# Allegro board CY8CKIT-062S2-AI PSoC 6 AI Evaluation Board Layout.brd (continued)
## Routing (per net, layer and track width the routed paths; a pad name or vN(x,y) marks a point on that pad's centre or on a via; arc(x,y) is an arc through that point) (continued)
N17076514: length 8
  TOP w0.15: R59.2 18.55,34.41 17.74,33.6 17.74,32 16.42,30.68 16.42,30 16.29,29.87 16.29,29.26 15.38,28.35 U1.N5
N17278110: length 0.9
  BOTTOM w0.15: U20.3 20.55,11.62 R19.2
N17278725: length 1.2
  TOP w0.15: R64.1 8.36,22.91 U3.4
N17278748: length 1.3
  TOP w0.15: U3.3 6.92,22.57 6.92,22.71 6.54,23.09 6.54,23.31 R65.1
N17279219: length 2.9
  TOP w0.15: v1(4.63,40.97) 4.28,41.33 R74.1 4.38,41.55 5.05,41.55 R73.2
  BOTTOM w0.15: v1(4.63,40.97) 4.63,41.27 5.12,41.76 U4.4
N17279342: length 5
  TOP w0.15: v1(29.85,43.99) 29.12,43.26 29.12,42.24 28.78,41.9 R82.1 28.78,41.3 29.32,40.76 R81.2
  BOTTOM w0.15: v1(29.85,43.99) 29.85,43.61 29.7,43.46 U5.4
N17289581: length 2
  BOTTOM w0.15: U7.5 27.04,35.03 27.41,35.03 27.59,34.85 27.9,34.85 28.44,35.39 R88.1
N17289597: length 1.7
  BOTTOM w0.15: R89.1 17.64,33.09 18.09,32.64 18.41,32.64 18.42,32.65 U7.2
N17289613: length 11.9
  BOTTOM w0.15: U7.3 18.33,33.92 18.25,33.83 18.25,33.63 18.55,33.32 19.64,33.32 19.86,33.54 19.86,34.67 19.99,34.8 20.18,34.8 20.31,34.67 20.31,34.05 20.44,33.92 20.72,33.92 20.96,34.16 20.96,34.87 20.68,35.16 20.05,35.16 19.45,35.76 18.22,35.76 17.81,35.36 17.81,34.52 17.64,34.34 R90.1
N17289629: length 1.7
  BOTTOM w0.15: R91.1 28.44,33.02 28,33.02 27.63,32.65 U7.7
N17305257: length 3.7
  TOP w0.229: L3.1 27.2,35.24 26.93,34.98 26.93,34.79 C248.1
  TOP w0.254: U17.31 26.1,35.09 26.61,34.59 C248.1
N17305261: length 3.7
  TOP w0.254: L3.2 26.74,37.64 26.45,37.64 25.79,36.98 24.9,36.98 24.54,36.63 U17.34
N17332525: length 3.4
  TOP w0.18: C246.2 21.39,43.48 L4.1 23.45,43.5 A2.4 A2.1
N17332695: length 9.3
  TOP w0.089: U17.18 23.64,30.21 23.94,29.92 24.16,29.92 24.85,29.24 24.85,28.51 v1(25.25,28.12)
  L04_SIG2 w0.089: v1(28.89,26.29) 28.58,25.98 27.97,25.98 26.06,27.89 25.48,27.89 v1(25.25,28.12)
  BOTTOM w0.089: v1(28.89,26.29) 28.89,26.68 29.16,26.95 TP17.1
N17332709: length 11.9
  TOP w0.089: U17.17 23.19,30 23.48,29.72 24.06,29.72 24.62,29.16 24.62,28.11 v1(24.46,27.95)
  L04_SIG2 w0.089: v1(18.95,26.64) 19.79,27.48 21.54,27.48 22.25,28.19 24.22,28.19 v1(24.46,27.95)
  BOTTOM w0.089: v1(18.95,26.64) 18.62,26.64 18.11,27.15 17.84,27.15 TP19.1
N17332795: length 4.6
  TOP w0.15: U17.10 v1(20.38,31.49)
  L03_SIG1 w0.157: v1(21.09,28.7) 21.09,29.41 20.81,29.69 20.81,31.06 v1(20.38,31.49)
  BOTTOM w0.15: TP28.1 21.27,28.88 v1(21.09,28.7)
N17363073: length 1.7
  TOP w0.15: v1(23.56,7.67) 23.79,7.44 J1.A5
  BOTTOM w0.15: R6.1 23.69,7.53 v1(23.56,7.67)
N17363075: length 1.6
  TOP w0.15: J1.B5 26.79,7.41 v1(26.55,7.65)
  BOTTOM w0.15: R5.1 26.4,7.49 v1(26.55,7.65)
N17373677: length 1.7
  TOP w0.15: J2.A5 8.47,7.57 v1(8.29,7.75)
  BOTTOM w0.15: R18.1 8.37,7.67 v1(8.29,7.75)
N17373681: length 1.6
  TOP w0.15: v1(11.29,7.67) 11.47,7.49 J2.B5
  BOTTOM w0.15: v1(11.29,7.67) 11.29,7.4 R17.1
N17374662: length 10.6
  TOP w0.15: v1(13.01,14.05) 13.32,14.35 13.32,14.54 R297.2 14.05,14.3 D8.K
  L04_SIG2 w0.157: v1(6.48,15.6) 6.79,15.29 11.36,15.29 11.59,15.52 12.07,15.52 13.01,14.58 v1(13.01,14.05)
  BOTTOM w0.15: v1(6.48,15.6) 6.25,15.36 U8.7
N17374666: length 5.2
  TOP w0.15: R1.1 13.45,10.51 13.45,11.98 15.05,13.59 D8.A
N17374668: length 11.6
  TOP w0.15: R2.2 13.24,8.99 13.69,8.54 14.22,8.54 v1(14.67,8.99) 14.95,9.27 R1.2
  L03_SIG1 w0.157: v1(14.67,8.99) 14.33,9.32 14.33,11.68 13.65,12.37 10.78,12.37 10.14,13 v1(10.14,14.12)
N17374688: length 10.3
  TOP w0.15: D11.K 12.89,12.62 v1(12.79,12.73) 12.4,13.11 12.4,14.48 12.71,14.79 R298.2
  L04_SIG2 w0.157: v1(8.01,14.4) 8.36,14.76 10.4,14.76 11.13,14.02 12.2,14.02 12.48,13.74 12.48,13.03 v1(12.79,12.73)
  BOTTOM w0.15: v1(8.01,14.4) 7.91,14.31 U8.9
N17374692: length 1
  TOP w0.15: D11.A R2.1
N17374847: length 1.8
  BOTTOM w0.15: R8.2 4.6,11.9 U8.1
N17374885: length 1
  BOTTOM w0.15: U8.14 6.25,11.73 6.41,11.58 6.41,11.26 R9.2
N17374979: length 5.9
  BOTTOM w0.15: R283.1 4.42,9 4.61,8.81 5.37,8.81 5.55,8.99 5.55,9.79 R13.1 5.54,9.87 5.28,10.13 5.28,10.27 5.15,10.4 5.15,11.04 5.3,11.19 5.52,11.19 R14.1 5.57,11.53 5.75,11.71 U8.15
N17374981: length 1
  BOTTOM w0.15: U8.12 8.28,12.81 R15.1
N17374983: length 1.1
  BOTTOM w0.15: R16.1 5.25,11.74 U8.16
N17378355: length 2.9
  BOTTOM w0.15: U11.10 11,12.45 10.67,12.78 R23.1 R21.2 10.67,14.32 10.78,14.43 10.78,14.92 C253.2
N17378650: length 1.2
  TOP w0.15: R26.2 27.37,10.03 27.14,10.26 D1.A
N17390542: length 0.9
  BOTTOM w0.15: R25.2 23.35,11.62 U21.3
N17394939: length 1.6
  BOTTOM w0.15: U11.6 11,9.8 10.49,9.29 R20.2
N17395527: length 3.6
  L04_SIG2 w0.157: v1(10.4,9.8) 10.95,9.25 v1(11.11,9.25)
  BOTTOM w0.15: R24.1 10.76,9.1 10.91,9.25 v1(11.11,9.25) ; v1(10.4,9.8) 10.31,9.88 10.12,9.88 9.97,10.03 R22.2 9.97,10.16 10.42,10.62 10.94,10.62 U11.7
N17444411: length 3.1
  TOP w0.15: U19.C2 18.32,22.13 18.86,22.66 20.71,22.66 C245.1
N17459450: length 2.2
  TOP w0.15: R100.1 23.42,38.42 24.05,39.06 Y3.O
N17461053: length 11.3
  TOP w0.15: U6.M5 21.06,16.39 19.89,15.21 19.89,14.51 19.71,14.33 19.71,14.07 v1(18.39,12.75)
  BOTTOM w0.15: v1(18.39,12.75) 17.98,13.16 17.98,14.25 18.29,14.56 18.29,16.41 17.25,17.45 TP16.1
N17461288: length 2.3
  TOP w0.15: C80.2 22.15,20.2 22.03,20.08 U6.L1
N17462113: length 5.4
  TOP w0.229: v1(15.02,16.64) 15.02,17.35 15.58,17.91 U15.4
  BOTTOM w0.229: v1(15.02,16.64) 15.02,16.63 C89.1 15.86,15.79 C88.1 16.23,15.99 16.6,15.62 17.05,15.62 17.45,16.02 FB12.2
N17462137: length 1.3
  TOP w0.15: R83.1 17.99,17.53 17.88,17.63 17.71,17.63 U15.3
N17489317: length 7.4
  TOP w0.15: R55.2 20.03,23.66 20.46,24.08 21.82,24.08 22.04,24.3 23.15,24.3 23.69,24.84 SW2.3 SW2.4
N17489457: length 1.3
  TOP w0.15: D2.A 14.37,18.72 R62.1
N17489487: length 1.2
  TOP w0.15: R63.1 12.66,18.33 D3.A
N17505741: length 12.3
  TOP w0.15: U17.8 v1(20.36,32.39)
  L03_SIG1 w0.157: v1(28.38,29.41) 28.01,29.78 v1(28.01,30.33)
  BOTTOM w0.15: v1(20.36,32.39) 20.37,32.39 20.76,32 20.76,31.01 21.09,30.68 22.17,30.68 22.68,30.18 25.21,30.18 25.39,29.99 25.76,29.99 26.1,30.33 v1(28.01,30.33) ; TP29.1 27.85,29.41 v1(28.38,29.41)
N17505744: length 13.8
  TOP w0.15: U17.9 19.63,31.94 v1(19.62,31.93)
  L03_SIG1 w0.157: v1(25.71,29.13) 25.13,28.55 24.52,28.55 23.4,27.43 19.9,27.43 19.49,27.84 19.49,29.62 19.18,29.93 19.18,31.25 19.62,31.69 v1(19.62,31.93)
  BOTTOM w0.15: TP27.1 25.46,28.88 v1(25.71,29.13)
N17505747: length 4.1
  TOP w0.15: U17.11 v1(19.85,31.04)
  BOTTOM w0.15: TP26.1 17.79,30.78 19.59,30.78 v1(19.85,31.04)
N17506574: length 2.9
  TOP w0.15: U18.12 11.39,23.37 11.59,23.57 12.21,23.57 12.67,23.11 12.67,22.49 R285.1
N17506591: length 3.2
  TOP w0.15: v1(8.87,22.48) 8.87,22.81 8.98,22.92 9.63,22.92 U18.1
  BOTTOM w0.15: R287.1 R286.1 8.26,22.4 8.34,22.48 v1(8.87,22.48)
N17531797: length 3.6
  BOTTOM w0.089: R86.1 18.11,32.34 18.22,32.23 18.62,32.23 19.07,31.78 U7.1
  BOTTOM w0.15: U7.1 18.26,31.38 18.1,31.54 R84.2
N17531826: length 2.7
  BOTTOM w0.15: U7.6 27.1,33.92 27.65,34.47 28.06,34.47 28.22,34.63 R85.2 R87.1
N17580471: length 1.6
  BOTTOM w0.15: C24.1 20.32,26.74 20.05,26.46 U2.53
N17581080: length 1.7
  BOTTOM w0.15: U2.42 17.96,21.31 C33.1
N17581130: length 2.2
  BOTTOM w0.114: U2.22 24.45,17.43 24.37,17.35 24.37,16.99 24.98,16.38 24.98,16.21 25.19,15.99 R35.2
N17581131: length 2.2
  BOTTOM w0.114: U2.23 24.05,17.44 24.14,17.35 24.14,16.9 24.75,16.29 24.75,16.21 24.54,15.99 R37.2
N17581135: length 1.6
  BOTTOM w0.15: U2.31 20.85,16.52 C34.1
N17592490: length 10.3
  TOP w0.15: R288.2 15.59,37.12 15.36,36.9 15.36,36.25 17.03,34.59 17.03,32.13 16.77,31.87 16.76,31.87 15.87,30.98 15.87,30.27 15.26,29.65 U1.N7
N17592497: length 9.9
  TOP w0.15: R289.2 14.61,38.13 14.71,38.03 14.71,37.31 14.5,37.09 14.5,36.64 15.66,35.48 15.66,32.59 15.69,32.55 v1(15.69,32.55) ; U1.L8 v1(13.94,30.63)
  L04_SIG2 w0.089: v1(13.94,30.63) 13.94,31.38 14.27,31.71 14.27,32.06 14.46,32.25 15.07,32.25 15.36,32.54 15.68,32.54 v1(15.69,32.55)
N17595841: length 20.3
  TOP w0.15: v1(29.68,20.32) 29.6,20.24 27.03,20.24 25.71,18.92 25.57,18.92 U6.E1
  L04_SIG2 w0.157: v1(17.56,23.41) 17.73,23.24 17.73,23 17.83,22.89 17.83,22.43 18.04,22.22 18.34,22.22 18.95,22.84 20.38,22.84 21.03,22.19 21.58,22.19 23.46,20.32 29.67,20.32 v1(29.68,20.32)
  BOTTOM w0.15: v1(17.56,23.41) 17.45,23.52 R294.2
N17595844: length 19.6
  TOP w0.15: v1(29.3,19.81) 29.17,19.94 27.16,19.94 25.93,18.7 25.85,18.7 U6.D1 ; v1(18.09,23.59) 18.57,23.59 R293.2
  L04_SIG2 w0.157: v1(29.3,19.81) 29.37,19.89 29.79,19.89 30.06,20.16 30.06,20.5 29.78,20.78 27.82,20.78 26.15,22.45 21.13,22.45 19.99,23.59 v1(18.09,23.59)
N17595847: length 20.5
  TOP w0.15: v1(29.45,18.97) 28.97,18.97 28.64,19.3 27.36,19.3 26.83,18.77 26.83,18.69 U6.B1 ; v1(15.37,22.51) 14.96,22.92 R292.2
  L04_SIG2 w0.157: v1(29.45,18.97) 28.69,18.97 28.35,19.31 27.38,19.31 27.38,19.3 23.94,19.3 22.16,21.08 21.48,21.08 21.03,21.53 21.03,21.7 20.21,22.51 19,22.51 18.45,21.96 17.79,21.96 17.58,22.18 15.71,22.18 15.38,22.51 v1(15.37,22.51)
N17595850: length 6.6
  TOP w0.15: U6.G1 24.04,18.39 25.18,19.53 25.56,19.53 26.91,20.88 28.03,20.88 28.71,21.56 28.71,21.85 R291.2
N17595911: length 2.7
  BOTTOM w0.15: U2.39 18.52,20.11 18.29,20.35 16.72,20.35 16.58,20.2 R295.1
N17595914: length 2.5
  TOP w0.15: v1(19.6,20.67) 19.2,20.67 18.88,20.35 R296.1
  BOTTOM w0.15: v1(19.6,20.67) 19.6,19.82 19.49,19.71 U2.38
N17604769: length 5.3
  TOP w0.15: R299.2 28.89,20.55 26.94,20.55 25.67,19.28 25.59,19.21 25.35,19.21 U6.F1
N17606878: length 1.2
  TOP w0.15: D12.A 32.06,6.92 32.06,6.17 R38.1
N17607574: length 14.9
  TOP w0.089: U1.G3 11.37,26.7 11.79,26.7 11.97,26.52 11.97,24.21 12.91,23.27 12.91,22.75 13.21,22.45 13.82,22.45 14.03,22.24 14.03,21.47 13.24,20.68 v1(13.24,20.35)
  L03_SIG1 w0.089: v1(10.24,18.04) 10.24,19.46 11.4,20.62 12.97,20.62 v1(13.24,20.35)
  BOTTOM w0.089: TP31.1 9.91,18.37 v1(10.24,18.04)
N172791730: length 3.3
  BOTTOM w0.15: R71.1 6.59,40.46 6.59,42.39 6.14,42.84 U4.1
N172792960: length 1.5
  BOTTOM w0.15: R79.1 28.94,40.4 28.94,40.77 28.61,41.1 U5.1
N173838130: length 1.6
  BOTTOM w0.15: U4.3 6.14,40.78 5.76,40.4 R72.1
N173838340: length 3.4
  L03_SIG1 w0.157: v1(28.61,42.67) 28.61,41.12 28.38,40.89 v1(28.13,40.89)
  BOTTOM w0.15: v1(28.61,42.67) 28.61,43.46 U5.3 ; R80.1 v1(28.13,40.89)

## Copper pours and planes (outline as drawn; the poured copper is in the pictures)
GND_EARTH on BOTTOM: 5,7.82 5.61,7.82 6.31,7.13 6.31,2.92 6.79,2.44 12.73,2.44 13.09,2.79 13.09,7.09 13.67,7.67 14.51,7.67 15.02,7.16 15.02,2.82 15.4,2.44 19.2,2.44 19.68,2.92 19.68,7.04 20.19,7.54 21.13,7.54 21.61,7.06 21.61,2.97 22.12,2.46 27.86,2.46 28.4,3 28.4,7.06 29.11,7.77 33.53,7.77 33.63,7.67 33.63,6.48 33.48,6.33 30.5,6.33 30.25,6.07 30.25,1.42 29.84,1.02 4.96,1.02 4.96,1.14 4.86,1.24 4.86,1.63 4.78,1.7 4.43,1.7 4.39,1.74 4.39,7.21
GND_SIGNAL on BOTTOM (solid shape): outline of 128 points within 2.92,41.57 5,43.65
GND_SIGNAL on BOTTOM (solid shape): outline of 128 points within 29.75,41.57 31.83,43.65
GND_SIGNAL on TOP: outline of 114 points within 1.02,1.01 33.75,44.75 ; 150 cut-outs
GND_SIGNAL on BOTTOM: outline of 102 points within 1.02,1.01 33.75,44.75 ; 172 cut-outs
GND_SIGNAL on L02_GND1: 31.04,44.74 31.38,44.74 31.39,44.75 32.38,44.75 33.35,44.35 33.75,43.38 33.75,2.38 33.35,1.41 32.38,1.01 2.38,1.01 1.42,1.41 1.02,2.38 1.02,43.38 1.41,44.34 2.38,44.74 31.04,44.74 ; 23 cut-outs
GND_SIGNAL on L03_SIG1: outline of 100 points within 1.02,1.01 33.75,44.75 ; 157 cut-outs
GND_SIGNAL on L04_SIG2: 31.39,44.75 32.38,44.75 33.35,44.35 33.75,43.38 33.75,40.4 33.53,40.18 32.38,40.18 32.92,39.65 33.73,39.65 33.75,39.67 33.75,36.61 33.65,36.7 32.92,36.7 32.38,36.17 33.5,36.17 33.75,35.93 33.75,25.22 33.3,25.22 32.84,24.77 33.4,24.77 33.75,24.42 33.75,22.37 33.35,21.97 31.72,21.97 32.23,21.46 33.6,21.46 33.75,21.61 33.75,20.09 31.22,20.09 30.91,19.79 30.91,19.25 31.29,19.64 33.48,19.64 33.75,19.37 33.75,4.66 33.45,4.37 32.41,4.37 32.87,3.91 33.75,3.91 33.75,2.38 33.35,1.41 32.38,1.01 2.38,1.01 1.42,1.41 1.02,2.38 1.02,22.53 1.12,22.63 3.38,22.63 3.61,22.4 3.81,22.61 3.81,22.81 3.25,23.37 1.02,23.37 1.02,35.99 1.19,36.17 2.39,36.17 1.73,36.83 1.02,36.83 1.02,39.65 1.88,39.65 2.41,40.18 1.22,40.18 1.02,40.39 1.02,43.38 1.41,44.34 2.38,44.74 31.04,44.74 31.04,44.74 31.38,44.74 ; 167 cut-outs
GND_SIGNAL on L05_GND2: 31.04,44.74 32.38,44.74 33.35,44.34 33.75,43.38 33.75,2.38 33.35,1.41 32.38,1.01 2.38,1.01 1.42,1.41 1.02,2.38 1.02,43.38 1.41,44.34 2.38,44.74 31.04,44.74 ; 23 cut-outs
VBAT_IN on TOP: 6.77,16.31 6.77,14.93 9.31,14.93 9.57,15.19 9.57,15.7 9.57,15.7 9.31,15.96 9.31,16.59 8.98,16.92 7.38,16.92
VBAT_IN on BOTTOM: 2.19,14.61 2.6,14.61 2.75,14.45 3.77,14.45 4.25,13.97 4.84,13.97 4.91,13.89 4.91,13.23 4.86,13.18 3.97,13.18 3.84,13.31 2.17,13.31 2.04,13.44 2.04,14.45
VBAT_IN on L04_SIG2: 5.41,18.11 8.56,18.11 9.14,17.53 9.14,17.12 8.94,17.32 8.51,17.32 8.31,17.12 8.89,17.12 9.14,16.87 9.14,15.85 8.84,15.55 6.58,15.55 4.11,13.08 2.26,13.08 2.03,13.31 2.03,14.43 2.26,14.66 3.3,14.66 4.27,15.62 4.27,16.97 ; 1 cut-out
VBUS_IN on TOP: 1.18,9.37 1.18,8.26 1.41,8.03 2.78,8.03 3.03,8.28 3.03,9.37 2.75,9.65 1.46,9.65
VBUS_IN on BOTTOM: 1.18,8.26 1.41,8.03 2.78,8.03 3.03,8.28 3.03,9.37 2.75,9.65 2.57,9.65 2.42,9.8 2.42,10.87 2.19,11.1 1.51,11.1 1.18,10.77
VBUS_IN on BOTTOM: 6.64,12.45 6.64,11.84 6.77,11.71 6.77,10.41 6.56,10.21 6.33,10.21 6.18,10.06 6.18,8.94 6.41,8.71 7.5,8.71 7.73,8.94 7.73,10.49 7.38,10.85 7.38,12.24 7.17,12.45
VBUS_IN on L04_SIG2: 6.37,8.51 6.51,8.64 7.54,8.64 7.8,8.91 7.8,11.05 7.39,11.46 1.6,11.46 1.17,11.02 1.17,8.76 1.42,8.51
VCC_1V8 on BOTTOM: 22.23,14.27 22.23,12.55 21.85,12.17 21.32,12.17 21.04,12.45 21.04,14.12 21.32,14.4 22.11,14.4
VCC_1V8 on L03_SIG1: 20.18,14.2 21.7,14.2 22.67,13.23 22.67,9.21 22.53,9.07 22.53,8.92 21.92,8.31 21.34,8.31 21.56,8.08 22.22,8.08 22.67,8.52 22.67,8.48 21.6,7.42 21.21,7.42 21.31,7.52 21.31,7.75 21.03,8.03 21.03,7.7 20.75,7.42 20.75,7.42 17.81,7.42 16.95,8.28 16.95,11.89 16.65,12.19 15.6,12.19 15.35,12.45 15.35,13.16 15.6,13.41 19.57,13.41 20.35,12.62 20.46,12.73 20.46,13.26 20,13.72 19.69,13.72 ; 2 cut-outs
VCC_3V3 on BOTTOM: 19.47,14.4 19.47,12.6 19.06,12.19 18.53,12.19 18.04,12.67 18.04,14.25 18.32,14.53 19.34,14.53
VCC_3V3 on L03_SIG1: 15.43,18.97 15.88,18.97 16.14,18.72 16.14,15.95 16.98,15.11 19.49,15.11 19.75,14.86 19.75,14.73 19.57,14.91 19.34,14.91 19.11,14.68 19.11,14.66 19.52,14.66 19.62,14.55 19.62,14.07 19.21,13.67 16.14,13.67 15.2,14.61 15.2,14.8 15.49,14.5 15.93,14.5 16.03,14.61 15.72,14.61 15.2,15.13 15.2,18.75
VCC_3V6 on BOTTOM: 13.09,12.04 13.09,15.16 12.99,15.27 12.99,15.95 13.09,16.05 13.85,16.05 14.39,15.52 14.39,12.32 14.11,12.04
VCC_3V6 on BOTTOM: 28.15,32.56 28.15,31.93 28.36,31.72 29.47,31.72 29.78,31.42 29.78,27.99 29.67,27.88 29.67,24.44 29.98,24.13 29.98,23.39 30.08,23.29 30.08,18.11 29.78,17.81 29.78,12.37 30.03,12.12 31.14,12.12 31.42,12.4 31.42,31.88 30.56,32.74 28.33,32.74
VCC_3V6 on BOTTOM: 19.41,10.11 19.41,9.3 19.21,9.09 18.42,9.09 18.22,9.3 18.22,11.28 18.75,11.81 19.08,11.81 19.26,11.63 19.26,10.26
VCC_3V6 on BOTTOM: 22.25,10.12 22.25,9.31 22.04,9.11 21.26,9.11 21.05,9.31 21.05,11.29 21.59,11.82 21.92,11.82 22.09,11.65 22.09,10.27
VCC_3V6 on L04_SIG2: 13.14,15.88 14.36,15.88 14.59,15.65 14.59,14.73 14.67,14.65 14.77,14.43 14.99,14.33 15.1,14.22 17.76,14.22 18.93,13.06 24.14,13.06 25.71,11.48 28.41,11.48 29.91,12.98 30.46,12.98 31.01,12.43 31.01,11.91 29.11,10.01 24.83,10.01 23.83,9.02 17.31,9.02 12.94,13.39 12.94,15.67
VIN on BOTTOM: 9.36,12.32 9.36,10.87 9.51,10.72 10.19,10.72 10.5,11.02 11.39,11.02 11.39,11.33 10.5,11.33 10.4,11.43 10.4,12.24 10.25,12.4 9.43,12.4
VIN on BOTTOM: 13.09,10.34 13.09,9.53 12.96,9.4 12.96,8.74 13.01,8.69 14.21,8.69 14.31,8.79 14.31,9.27 13.9,9.68 13.9,10.34
VIN on L04_SIG2: 10.22,10.21 11.01,10.21 11.31,9.91 12.48,9.91 12.58,9.8 12.58,8.92 12.79,8.71 14,8.71 14.18,8.89 14.18,11.23 12.81,12.6 10.17,12.6 9.84,12.27 9.84,10.59
KP_VBUS on TOP: 22.16,8.26 22.16,8.03 22.34,7.85 22.34,6.15 22.95,6.15 22.95,7.7 23.22,7.98 23.22,8.26 23.05,8.43 22.34,8.43
KP_VBUS on TOP: 27.14,6.15 27.14,7.57 26.62,8.09 26.62,9.48 26.75,9.6 27.43,9.6 27.51,9.53 27.51,8.71 27.77,8.45 27.77,7.8 27.72,7.75 27.72,6.15
KP_VBUS on BOTTOM: 1.28,6.48 1.28,4.98 1.53,4.72 3.01,4.72 3.26,4.98 3.26,6.48 2.98,6.76 1.56,6.76
KP_VBUS on BOTTOM: 24.47,5.14 22.82,5.14 22.49,4.81 22.49,2.83 22.64,2.68 24.62,2.68 24.77,2.83 24.77,4.84
KP_VBUS on L04_SIG2: 16.71,4.55 11.66,4.55 11.4,4.29 11.05,4.29 10.79,4.55 6.12,4.55 4.04,6.63 2.73,6.63 2.57,6.48 2.57,4.85 4.48,2.95 22.6,2.95 23.72,4.07 23.72,5.59 23.7,5.61 23.7,5.89 24.31,6.5 25.46,6.5 25.46,6.5 27.71,6.5 27.91,6.71 27.91,8.31 27.74,8.48 20.65,8.48 ; 1 cut-out
P6_VBUS on TOP: 11.82,6.15 11.82,7.57 11.41,7.98 11.41,8.38 11.59,8.56 12.28,8.56 12.46,8.38 12.46,7.8 12.4,7.75 12.4,6.15
P6_VBUS on TOP: 1.25,5.33 1.51,5.08 2.6,5.08 2.85,5.33 2.85,7.14 2.65,7.34 1.46,7.34 1.25,7.14
P6_VBUS on TOP: 6.84,8.23 6.84,8 7.02,7.82 7.02,6.12 7.63,6.12 7.63,7.67 7.91,7.95 7.91,8.23 7.73,8.41 7.02,8.41
P6_VBUS on BOTTOM: 9.15,5.16 7.5,5.16 7.17,4.83 7.17,2.84 7.32,2.69 9.31,2.69 9.46,2.84 9.46,4.85
P6_VBUS on L03_SIG1: 5.75,8.48 7.8,8.48 8.04,8.25 8.04,7.67 8.57,7.14 8.57,4.37 7.86,3.66 4.28,3.66 3.97,3.96 2.09,3.96 1.23,4.83 1.23,7.14 1.58,7.49 4.76,7.49
P6_VBUS on L04_SIG2: 8.18,8.48 13.7,8.48 13.93,8.26 13.93,6.69 13.44,6.2 7.16,6.2 6.65,6.71 6.65,8.33 6.81,8.48 7.62,8.48 7.62,8.43 7.87,8.43 7.98,8.33 7.98,7.75 8.28,8.05 8.28,8.38 ; 2 cut-outs
N17332525 on TOP: 22.68,42.94 22.68,43.64 24.18,43.64 24.18,42.94
N17374668 on BOTTOM: 7.07,13.89 7.07,13.21 7.12,13.16 8.54,13.16 8.85,12.85 10.25,12.85 10.37,12.98 10.37,14.2 10.22,14.35 9.17,14.35 8.79,13.97 7.15,13.97
N17393871 on BOTTOM: 13.09,11.53 14.49,11.53 14.64,11.38 17.36,11.38 17.48,11.51 17.48,12.47 17.38,12.57 14.89,12.57 14.18,11.86 13.12,11.86 13.09,11.84
N17393876 on BOTTOM: 13.09,10.52 14.11,10.52 14.26,10.36 14.26,9.53 14.39,9.4 17.43,9.4 17.51,9.47 17.51,10.41 17.08,10.85 13.09,10.85

Small or netless copper shapes (teardrops, artwork), in the pictures only: 6 on TOP, 3 on BOTTOM, 2 on L04_SIG2

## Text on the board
BOTTOM: BOTTOM
Ref Des/Assembly Bottom: ASSEMBLY DRAWING BOTTOM
Package Geometry/Pastemask Bottom: PASTE MASK BOTTOM
Ref Des/Silkscreen Bottom: 1 | 4 | 5 | 8 | MIC | PDM | VBAT.IN | P6.VBS | VCCD | GND | 3V3 | VTARG | VIN | KP.VBS | VDDIO.1YN | MODE | KP3 | VBAT | CLK | RES | VDD | DIO | 3V6 | VBUS.IN | REV 03 | CY8CKIT-062S2-AI | 600-60699-01 | SILKSCREEN BOTTOM
User.Comments: SOLDER MASK TOP | SOLDER MASK BOTTOM
TOP: TOP
Ref Des/Assembly Top: ASSEMBLY DRAWING TOP
Package Geometry/Pastemask Top: PASTE MASK TOP
Ref Des/Silkscreen Top: 4 | 11 | J17 | DIGI | TX | RX | SCL | SDA | GND | 3V3 | P6-USB | USR2 | CHG | PG | USR1 | KP3-USB | PWR | P9.6 | P9.0 | P9.4 | P9.2 | P9.7 | P9.1 | STS | KP3 | USER | RESET | P9.3 | P9.5 | TM | PSoC   6 AI | EVALUATION KIT | + | - | SILKSCREEN TOP
L02_GND1: L02_GND1
L03_SIG1: L03_SIG1
L04_SIG2: L04_SIG2
L05_GND2: LO5_GND2
DIMENSION: x4
User.23: TM
User.24: 10. A2 - THE ANTENNA REGION WITH COPPER CLEARANCE (RECOMMENDED BY QUALITY TEAM FOR PRODUCTION BUILD) | 1. SPECIFICATIONS/TOLERANCES: | 2 | 3. DRILLING: | 4. SOLDER MASK: | 5. MARKING: | 6. ELECTRICAL TEST: | 7 | 8. IMPEDANCE: | 9. IF PANELIZATION SPECIFICATIONS ARE PROVIDED, THE PCBS SHALL BE DELIVERED IN | A. FABRICATE PER IPC-6012, CLASS 2, USING PROVIDED DATA FILES | B. ALL SPECIFICATIONS USED SHALL BE PER THEIR LATEST REVISIONS. | C. THE DIMENSIONS OF CIRCUIT FEATURES IN THE PROVIDED DATA MAY BE ADJUSTED | D. REMOVE ALL BURRS AND BREAK SHARP EDGES, .381 [.015] MAX RADIUS. | E. PARENTHETICAL INFORMATION IS FOR REFERENCE ONLY. | F. REPAIR OF PCB DEFECTS IS NOT PERMITTED. | DIELECTRIC MATERIAL: | A. DIELECTRIC MATERIAL SHALL BE PER IPC-4101/99, /124, /126 OR /129 | B. MINIMUM DIELECTRIC THICKNESS SHALL BE .051 [.002] FOR REFERENCED STACK-UP | C. SEE LAYER STACK-UP FOR REQUIRED COPPER WEIGHTS AND THE FINISHED PCB | D. FINISHED PCB THICKNESS SHALL BE MEASURED OVER LANDS AND/OR | A. VIA DIAMETERS (TOL. = +.051/- DRILL DIAMETER [+.0020/- DRILL DIAMETER]) | B. LAYER-TO-LAYER MISREGISTRATION SHALL BE .127 [.005] MAXIMUM. | A. APPLY LPI SOLDER MASK USING PROVIDED DATA. | B. SOLDER MASK SHALL BE PER IPC-SM-840, CLASS T, COLOR BLUE | C. THE DIMENSIONS OF SOLDER MASK-DEFINED PADS ON PLANES AND/OR WIDE | A. MARK PCB PER PROVIDED DATA USING SILKSCREEN OR AUTOMATED INJET | B. SUPPLIER ID AND TRACEABILITY INFORMATION SHALL BE APPLIED USING | C. INK SHALL NOT BE APPLIED TO ANY SOLDERABLE SURFACE. | A. DESIGN VERIFICATION SHALL BE DONE PRIOR TO PCB FABRICATION USING | B. ALL PCBS SHALL BE 100% ELECTRICALLY TESTED FOR OPENS AND SHORTS | C. APPLY TEST STAMP IN NON-LEGEND AREA ON REAR SIDE OF PCB; OK TO APPLY | FINAL FINISH: | A. FINAL FINISH SHALL BE ELECTROLESS NICKEL/IMMERSION GOLD (ENIG) PER IPC-4552. | A. IMPEDANCE TOLERANCE SHALL BE +/- 10%. | B. SEE LAYER STACK-UP FOR IMPEDANCE REQUIREMENTS. | PANEL FORM. HOWEVER, THESE SPECIFICATIONS MAY BE CHANGED AS REQUIRED BY THE | CONTRACT MANUFACTURER TO SUPPORT VOLUME ASSEMBLY REQUIREMENTS. | 600-60699-01_03.TGZ OR 600-60699-01_03.ZIP. | ONLY TO COMPENSATE FOR PROCESS TOLERANCES; ADDING, REMOVING OR RELOCATING | CIRCUIT FEATURES, INCLUDING NON-FUNCTIONAL PADS, IS NOT ALLOWED, AND THE | DESIGN OF ALL PLANE STRUCTURES MUST BE MAINTAINED TO ENSURE PROPER | ELECTRICAL PERFORMANCE. | (RoHS COMPLIANT EPOXY-GLASS). | DIMENSIONS OF.076 [.003] OR GREATER; IPC-6012 REQUIREMENTS SHALL OTHERWISE | APPLY. SINGLE-PLY CONSTRUCTION IS ALLOWED. | THICKNESS. IF SPECIFIED, 1/3 OZ. STARTING FOIL MAY BE ACHIEVED BY 1/2 OZ. | FOIL REDUCTION. | CONDUCTORS NOT COVERED BY SOLDER MASK. | SHALL BE VERIFIED BEFORE PLATING; ALL OTHER HOLE DIAMETERS SHALL BE | VERIFIED AT FINAL INSPECTION. | CONDUCTORS SHALL NOT BE MODIFIED. | PROCESSING WITH PERMANENT, NON-CONDUCTIVE INK, COLOR WHITE. | PERMANENT, NON-CONDUCTIVE INK, COLOR WHITE. | SUPPLIED VALOR ODB++ DATABASE, OR GERBER DATA AND AN IPC-D-356 NETLIST. | USING PROVIDED DATA. | TO PANEL RAILS IF SPACE DOES NOT PERMIT. | NOTES: UNLESS OTHERWISE SPECIFIED
User.25: L05 - GND2 | L06 - BOTTOM | 1.26 | 1.85 | -- | 50E | --- | 5.9 | 05 | ----- | 02 | 90E | ---/--- | 4.5/5.5 | 4.5/4.5 | (.XXXX) | REF | LAYER
User.29: 2
User.30: TM
User.31: DIMENSIONS IN MM [INCH]
User.45: PROJECT: | DRAWN BY: | LAYER: | DWG NO: | REV: | DATE: | TM | Am Campeon 1-15 | Infineon Technologies AG | 85579 NEUBIBERG - GERMANY | CY8CKIT-062S2-AI PSoC  6 AI EVALUATION KIT | 620-60699-01 | SANTHOSH R | 03 | 15/04/24 | FIGURE | FINISHED_SIZE | 8.0 | 39.37 | 25.59 | 31.5 | 118.11 | 55.12x23.62 | 66.93x23.62 | DRILLED_SIZE | - | ROTATION | 90.000 | DRILL CHART: TOP to BOTTOM | ALL UNITS ARE IN MILS | FINISHED_TOL | +3.0/-3.0 | +2.0/-2.0 | DRILLED_TOL | PLATED | NON-PLATED | QTY | 637 | 15 | 4 | 2
